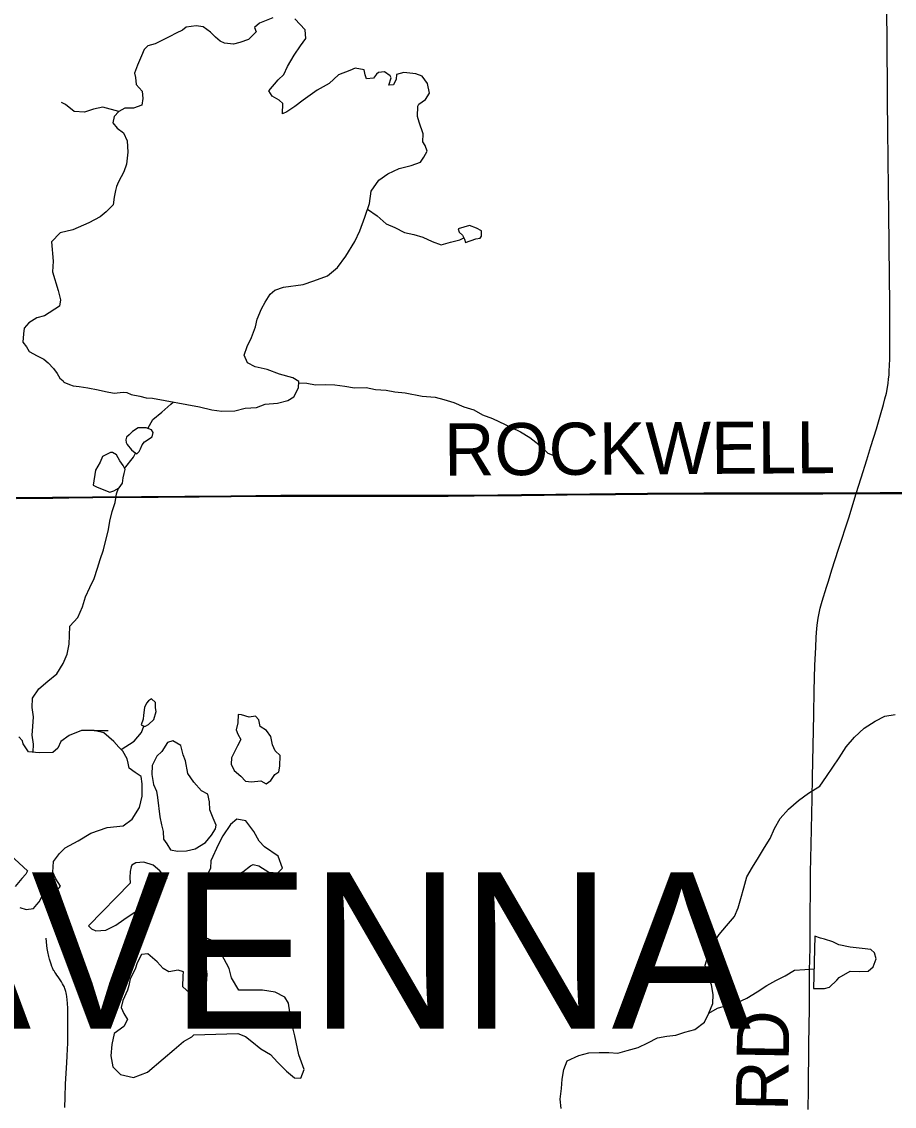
# Model space of a CAD drawing. Extents: x 0 to 34, y 0 to 22.
# Drawn here: x 24.299 to 25.25, y 14.945 to 16.128 of the extents above; entities that cross this region are included whole.
import ezdxf

# ---------------------------------------------------------------- set-up
doc = ezdxf.new("R2010")
doc.units = 0
for name, color, linetype in [('GM_X_Corporation', 7, 'Continuous'), ('GM_X_County_Road', 7, 'Continuous'), ('GM_X_County_Road_Text', 7, 'Continuous'), ('GM_X_Minor_Lake', 7, 'Continuous'), ('GM_X_Minor_River', 7, 'Continuous'), ('GM_X_Township_Road', 7, 'Continuous'), ('GM_X_Township_Text', 7, 'Continuous')]:
    doc.layers.add(name, color=color, linetype=linetype)

msp = doc.modelspace()

# ---------------------------------------------------------------- linework, layer by layer
at = {"layer": 'GM_X_Corporation'}
for points in [[(25.2604, 15.6138), (25.235, 15.6138), (25.2084, 15.6136), (25.172, 15.6134), (25.1329, 15.6134), (25.118, 15.6134), (25.0752, 15.6136), (25.0424, 15.6134), (24.9809, 15.6131), (24.9461, 15.6128), (24.9181, 15.6126), (24.8436, 15.6117), (24.792, 15.6111), (24.7634, 15.611), (24.7274, 15.6109), (24.7019, 15.6109), (24.6523, 15.6109), (24.6393, 15.6109), (24.6208, 15.611), (24.5813, 15.6109), (24.5268, 15.6104), (24.492, 15.61), (24.4765, 15.6099), (24.4473, 15.6097), (24.4292, 15.6096), (24.3758, 15.6093), (24.3497, 15.6089), (24.3323, 15.6087), (24.2926, 15.6084)], [(24.2926, 15.6084), (24.3323, 15.6087), (24.3497, 15.6089), (24.3758, 15.6093), (24.4292, 15.6096), (24.4473, 15.6097), (24.4765, 15.6099), (24.492, 15.61), (24.5268, 15.6104), (24.5813, 15.6109), (24.6208, 15.611), (24.6393, 15.6109), (24.6523, 15.6109), (24.7019, 15.6109), (24.7274, 15.6109), (24.7634, 15.611), (24.792, 15.6111), (24.8436, 15.6117), (24.9181, 15.6126), (24.9461, 15.6128), (24.9809, 15.6131), (25.0424, 15.6134), (25.0752, 15.6136), (25.118, 15.6134), (25.1329, 15.6134), (25.172, 15.6134), (25.2084, 15.6136), (25.235, 15.6138), (25.2604, 15.6138)]]:
    msp.add_lwpolyline(points, dxfattribs=at)
at = {"layer": 'GM_X_County_Road'}
for points in [[(25.2086, 15.6131), (25.2141, 15.6303), (25.2203, 15.6499), (25.2248, 15.6645), (25.2308, 15.6839), (25.2353, 15.6991), (25.2385, 15.7103), (25.2401, 15.7164), (25.2416, 15.7225), (25.2428, 15.7288), (25.2435, 15.7334), (25.2441, 15.738), (25.2446, 15.7426), (25.2448, 15.7465), (25.2453, 15.7598), (25.2454, 15.7669), (25.2454, 15.7757), (25.2454, 15.7911), (25.2453, 15.8193), (25.2445, 15.8826), (25.2444, 15.9209), (25.2441, 15.9449), (25.2436, 15.9788), (25.2433, 16.0086), (25.2431, 16.0193), (25.243, 16.0319), (25.2427, 16.0626), (25.2425, 16.0936), (25.242, 16.153)], [(25.2086, 15.6131), (25.2352, 15.6132), (25.2606, 15.6132), (25.2829, 15.6134), (25.309, 15.6134), (25.3301, 15.6135), (25.4755, 15.6146), (25.5271, 15.6148), (25.5526, 15.615), (25.7197, 15.6165), (25.7905, 15.6172), (25.849, 15.6177), (26.0069, 15.6183)], [(24.2928, 15.6079), (24.3325, 15.6082), (24.3499, 15.6084), (24.376, 15.6087), (24.4295, 15.6091), (24.4475, 15.6092), (24.4767, 15.6094), (24.4922, 15.6095), (24.527, 15.6098), (24.5815, 15.6103), (24.621, 15.6104), (24.6395, 15.6104), (24.6525, 15.6104), (24.7021, 15.6104), (24.7276, 15.6103), (24.7636, 15.6104), (24.7922, 15.6105), (24.8438, 15.6112), (24.9183, 15.612), (24.9463, 15.6122), (24.9811, 15.6125), (25.0426, 15.6128), (25.0754, 15.613), (25.1182, 15.6129), (25.1331, 15.6128), (25.1722, 15.6129), (25.2086, 15.6131)], [(25.1564, 14.9415), (25.1565, 14.9632), (25.1571, 15.0123), (25.1576, 15.0521), (25.1578, 15.0806), (25.1579, 15.0931), (25.1584, 15.1179), (25.1585, 15.134), (25.1585, 15.152), (25.1586, 15.1632), (25.1588, 15.1713), (25.159, 15.1998), (25.1596, 15.2303), (25.1606, 15.2806), (25.1609, 15.3038), (25.1625, 15.3723), (25.163, 15.3983), (25.1637, 15.4256), (25.1645, 15.4456), (25.165, 15.456), (25.1655, 15.4618), (25.1662, 15.4695), (25.1672, 15.4772), (25.1683, 15.4828), (25.1695, 15.488), (25.1717, 15.4957), (25.1763, 15.5112), (25.1783, 15.5177), (25.1822, 15.5301), (25.1895, 15.5525), (25.2006, 15.5868), (25.2086, 15.6131)]]:
    msp.add_lwpolyline(points, dxfattribs=at)
at = {"layer": 'GM_X_Minor_Lake'}
for p, q in [((24.7827, 15.887), (24.794, 15.8908)), ((24.4411, 15.7171), (24.4923, 15.7076)), ((24.4136, 15.6668), (24.4182, 15.6609)), ((24.381, 15.6203), (24.3946, 15.6147)), ((24.4324, 15.3799), (24.4313, 15.3715)), ((24.5338, 15.3382), (24.5275, 15.3249)), ((24.4468, 15.2818), (24.4493, 15.2606)), ((24.3458, 15.2268), (24.3601, 15.2345)), ((24.5131, 15.2307), (24.5049, 15.2125)), ((24.4375, 15.1638), (24.4573, 15.1939)), ((25.1637, 15.1303), (25.1623, 15.0734)), ((24.4863, 15.0227), (24.5344, 15.0242))]:
    msp.add_line(p, q, dxfattribs=at)
for points in [[(24.5149, 16.1064), (24.51, 16.1109), (24.5046, 16.1162), (24.4966, 16.1222), (24.4887, 16.1233), (24.4781, 16.1217), (24.474, 16.1186), (24.4672, 16.1151), (24.46, 16.1117), (24.4442, 16.1036), (24.4362, 16.1016), (24.4321, 16.0974), (24.4291, 16.0906), (24.4247, 16.0803), (24.4217, 16.0716), (24.4225, 16.067), (24.4233, 16.0594), (24.4298, 16.0519), (24.4306, 16.0439), (24.4296, 16.0367), (24.4205, 16.0336), (24.411, 16.0336), (24.4046, 16.0297), (24.3994, 16.0244), (24.3979, 16.0175), (24.4025, 16.0115), (24.4097, 16.0066), (24.4136, 15.9979), (24.4144, 15.9854), (24.413, 15.9725), (24.4101, 15.9641), (24.4041, 15.9531), (24.4019, 15.9481), (24.4008, 15.9436), (24.3993, 15.9364), (24.3982, 15.928), (24.3907, 15.9204), (24.3843, 15.915), (24.3719, 15.9085), (24.3545, 15.9008), (24.3406, 15.8976), (24.3312, 15.8877), (24.3329, 15.8665), (24.3322, 15.8551), (24.3384, 15.8346), (24.3408, 15.8244), (24.3397, 15.8176), (24.3235, 15.8068), (24.3152, 15.8049), (24.3065, 15.7995), (24.3013, 15.7934), (24.3006, 15.7873), (24.2999, 15.7782), (24.3037, 15.7733), (24.3068, 15.768), (24.3155, 15.7632), (24.3227, 15.7598), (24.3273, 15.7557), (24.3334, 15.7497), (24.3372, 15.744), (24.3403, 15.7391), (24.3437, 15.7361), (24.3445, 15.7346), (24.3506, 15.732), (24.3547, 15.7305), (24.3612, 15.7298), (24.3706, 15.7283), (24.382, 15.7261), (24.39, 15.7243), (24.3995, 15.7228), (24.4093, 15.7237), (24.4131, 15.7233), (24.418, 15.7211), (24.4275, 15.7193), (24.4343, 15.7174), (24.4411, 15.7171)], [(24.4923, 15.7076), (24.5059, 15.7043), (24.5169, 15.7029), (24.5309, 15.7034), (24.5423, 15.7061), (24.5548, 15.707), (24.5642, 15.7108), (24.5774, 15.7117), (24.5888, 15.7148), (24.5952, 15.7187), (24.6004, 15.7286), (24.6007, 15.7354), (24.5942, 15.7395), (24.5798, 15.7432), (24.5662, 15.7484), (24.5533, 15.7513), (24.5449, 15.7558), (24.5411, 15.7641), (24.5444, 15.7736), (24.5492, 15.7832), (24.5537, 15.7949), (24.5555, 15.8033), (24.56, 15.8147), (24.5641, 15.822), (24.5697, 15.8307), (24.5746, 15.8349), (24.584, 15.8384), (24.6056, 15.8412), (24.6173, 15.8451), (24.632, 15.8505), (24.6429, 15.8597), (24.6519, 15.8719), (24.662, 15.8879), (24.6672, 15.8997), (24.6727, 15.9146), (24.6779, 15.9294), (24.6797, 15.9431), (24.6879, 15.9549), (24.6977, 15.9618), (24.7102, 15.9676), (24.7234, 15.9711), (24.7336, 15.9746), (24.7373, 15.9799), (24.7407, 15.9864), (24.7387, 15.9928), (24.7361, 15.9966), (24.7364, 16.0053), (24.7321, 16.0182), (24.7302, 16.0242), (24.7305, 16.0356), (24.7316, 16.0379), (24.7391, 16.0429), (24.7432, 16.0497), (24.7412, 16.0603), (24.7355, 16.0683), (24.7283, 16.0709), (24.7154, 16.0723), (24.7075, 16.0703), (24.7068, 16.065), (24.7042, 16.0589), (24.6989, 16.0585), (24.7015, 16.0665), (24.7003, 16.0688), (24.6942, 16.0729), (24.6878, 16.0725), (24.6855, 16.0705), (24.6822, 16.0663), (24.6746, 16.0655), (24.673, 16.0697), (24.6722, 16.0754), (24.6624, 16.0772), (24.6564, 16.0745), (24.6439, 16.0698), (24.6338, 16.0603), (24.6209, 16.053), (24.6055, 16.0422), (24.5965, 16.0353), (24.5878, 16.0296), (24.5829, 16.0273), (24.5832, 16.0387), (24.5794, 16.042), (24.5718, 16.0465), (24.568, 16.0522), (24.5781, 16.0644), (24.5845, 16.0701), (24.5886, 16.0789), (24.5957, 16.0911), (24.6028, 16.1014), (24.6084, 16.1094), (24.6076, 16.1189), (24.5965, 16.1309)], [(24.5723, 16.1319), (24.5579, 16.1261), (24.5523, 16.1215), (24.5542, 16.1166), (24.546, 16.1085), (24.5365, 16.1051), (24.5297, 16.1031), (24.5199, 16.1045), (24.5149, 16.1064)], [(24.794, 15.8908), (24.7986, 15.8916), (24.8001, 15.8939), (24.8, 15.8996), (24.7947, 15.9026), (24.7871, 15.9056), (24.7746, 15.9017), (24.7758, 15.8983), (24.7792, 15.8949), (24.7815, 15.8907), (24.7827, 15.887)], [(24.4182, 15.6609), (24.4204, 15.6589), (24.4242, 15.6563), (24.4268, 15.659), (24.4283, 15.662), (24.4298, 15.6662), (24.4324, 15.6696), (24.4407, 15.675), (24.4418, 15.6796), (24.4403, 15.6826), (24.4342, 15.6848), (24.4255, 15.6847), (24.4195, 15.6809), (24.4157, 15.6771), (24.4127, 15.6748), (24.412, 15.6717), (24.4124, 15.6687), (24.4136, 15.6668)], [(24.3946, 15.6147), (24.3992, 15.6163), (24.4048, 15.6194), (24.4085, 15.6243), (24.4093, 15.6304), (24.4104, 15.6349), (24.4115, 15.6395), (24.4092, 15.6437), (24.4057, 15.6489), (24.4019, 15.6554), (24.3977, 15.658), (24.3954, 15.658), (24.3867, 15.6537), (24.3841, 15.6473), (24.3789, 15.6385), (24.3764, 15.6222), (24.381, 15.6203)], [(24.4313, 15.3715), (24.431, 15.367), (24.4288, 15.3609), (24.433, 15.359), (24.4367, 15.3613), (24.4427, 15.3667), (24.4453, 15.3754), (24.4445, 15.3796), (24.4445, 15.3853), (24.4403, 15.3891), (24.4369, 15.3871), (24.4347, 15.3845), (24.4324, 15.3799)], [(24.5275, 15.3249), (24.5271, 15.3181), (24.5302, 15.3112), (24.5375, 15.3049), (24.5428, 15.2996), (24.5492, 15.2989), (24.5595, 15.2997), (24.5652, 15.2967), (24.5704, 15.3002), (24.5745, 15.3067), (24.5791, 15.3097), (24.5801, 15.3158), (24.5804, 15.3276), (24.5751, 15.3324), (24.572, 15.3392), (24.5704, 15.3483), (24.5655, 15.3547), (24.5586, 15.3592), (24.557, 15.3664), (24.5536, 15.3702), (24.5468, 15.3694), (24.5381, 15.372), (24.5347, 15.3723), (24.5344, 15.3632), (24.5325, 15.3556), (24.5341, 15.3507), (24.5375, 15.3451), (24.5338, 15.3382)], [(24.3601, 15.2345), (24.3741, 15.2429), (24.3918, 15.2488), (24.4092, 15.2508), (24.419, 15.2581), (24.4272, 15.2706), (24.4298, 15.2832), (24.43, 15.2965), (24.4288, 15.3044), (24.4224, 15.3089), (24.4159, 15.3138), (24.4147, 15.3191), (24.4136, 15.324), (24.4089, 15.3323), (24.4044, 15.3365), (24.399, 15.3429), (24.388, 15.3523), (24.3777, 15.3548), (24.3637, 15.3547), (24.3505, 15.3493), (24.3411, 15.3428), (24.3378, 15.3356), (24.3325, 15.3306), (24.3177, 15.3305), (24.306, 15.3315), (24.3003, 15.3402), (24.2995, 15.3436), (24.2953, 15.3478)], [(24.4493, 15.2606), (24.4512, 15.2519), (24.4528, 15.2447), (24.4532, 15.2363), (24.4567, 15.2311), (24.4609, 15.2246), (24.4685, 15.2232), (24.4783, 15.2236), (24.4878, 15.2256), (24.4991, 15.2325), (24.5054, 15.2405), (24.5099, 15.2474), (24.5106, 15.2516), (24.5072, 15.2591), (24.5037, 15.2682), (24.5032, 15.2769), (24.5017, 15.2852), (24.4948, 15.289), (24.4864, 15.2984), (24.4799, 15.3078), (24.4772, 15.3215), (24.4748, 15.3283), (24.4721, 15.3385), (24.4634, 15.3434), (24.4577, 15.3418), (24.4513, 15.3319), (24.4461, 15.3269), (24.4409, 15.3166), (24.4406, 15.3068), (24.4422, 15.2958), (24.4456, 15.2886), (24.4468, 15.2818)], [(24.5049, 15.2125), (24.5046, 15.2045), (24.5012, 15.1976), (24.5062, 15.1916), (24.5172, 15.1917), (24.527, 15.1944), (24.5398, 15.2006), (24.5481, 15.2071), (24.5511, 15.2086), (24.5572, 15.2072), (24.5682, 15.2004), (24.578, 15.1994), (24.5829, 15.2047), (24.5783, 15.2176), (24.5634, 15.2277), (24.5577, 15.2341), (24.5516, 15.2447), (24.5431, 15.2564), (24.5333, 15.2582), (24.5261, 15.2521), (24.5179, 15.2399), (24.5131, 15.2307)], [(24.2964, 15.1616), (24.3036, 15.1594), (24.3115, 15.1606), (24.3149, 15.1651), (24.3175, 15.1678), (24.3216, 15.1754), (24.3204, 15.1811), (24.3208, 15.186), (24.3337, 15.1778), (24.3393, 15.1831), (24.3408, 15.185), (24.3359, 15.193), (24.3324, 15.2001), (24.3334, 15.2119), (24.3398, 15.2207), (24.3458, 15.2268)], [(24.2865, 15.2188), (24.3048, 15.2018), (24.3029, 15.198), (24.2988, 15.1934), (24.2916, 15.1847)], [(24.4573, 15.1939), (24.4535, 15.1965), (24.4493, 15.2018), (24.4421, 15.2078), (24.4319, 15.2111), (24.4232, 15.2103), (24.4186, 15.208), (24.4179, 15.2061), (24.4168, 15.2008), (24.4165, 15.1943), (24.4169, 15.1883), (24.3715, 15.1417), (24.3745, 15.1383), (24.3795, 15.1364), (24.3904, 15.1369), (24.4014, 15.1423), (24.41, 15.1488), (24.4213, 15.1561), (24.4292, 15.1599), (24.4375, 15.1638)], [(24.5344, 15.0242), (24.5427, 15.0209), (24.5496, 15.0156), (24.5595, 15.0077), (24.5698, 15.0014), (24.5774, 14.9931), (24.5873, 14.9833), (24.5961, 14.9758), (24.6029, 14.9755), (24.6066, 14.985), (24.6008, 15.0009), (24.5965, 15.0217), (24.5926, 15.0376), (24.5894, 15.0573), (24.5855, 15.0641), (24.5749, 15.0693), (24.5613, 15.0715), (24.551, 15.0714), (24.5355, 15.0716), (24.5275, 15.0849), (24.5247, 15.0951), (24.5163, 15.1109), (24.5109, 15.1192), (24.5052, 15.126), (24.4968, 15.1297), (24.492, 15.1244), (24.4951, 15.113), (24.499, 15.1006), (24.5006, 15.0888), (24.4999, 15.079), (24.4943, 15.0725), (24.4814, 15.0686), (24.4742, 15.0753), (24.4748, 15.0871), (24.4752, 15.0917), (24.4691, 15.0935), (24.4589, 15.0915), (24.4528, 15.0953), (24.4463, 15.1024), (24.436, 15.1111), (24.4292, 15.1103), (24.4244, 15.1015), (24.4222, 15.0943), (24.417, 15.084), (24.4155, 15.0768), (24.414, 15.0715), (24.4088, 15.0604), (24.407, 15.0525), (24.4101, 15.046), (24.4139, 15.0396), (24.4098, 15.032), (24.3993, 15.0243), (24.3967, 15.0122), (24.3957, 15), (24.398, 14.9879), (24.4064, 14.9797), (24.4205, 14.9763), (24.4359, 14.9822), (24.4528, 14.9967), (24.4649, 15.007), (24.475, 15.0154), (24.4841, 15.0208), (24.4863, 15.0227)], [(25.1623, 15.0734), (25.174, 15.0735), (25.1797, 15.075), (25.1875, 15.0823), (25.1902, 15.0854), (25.2022, 15.0923), (25.2124, 15.092), (25.2219, 15.0921), (25.2272, 15.097), (25.2305, 15.1058), (25.2286, 15.1122), (25.2247, 15.116), (25.2153, 15.117), (25.202, 15.1184), (25.1899, 15.121), (25.1831, 15.1244), (25.1743, 15.127), (25.1698, 15.1284), (25.1637, 15.1303)]]:
    msp.add_lwpolyline(points, dxfattribs=at)
at = {"layer": 'GM_X_Minor_River'}
for points in [[(24.4046, 16.0297), (24.3872, 16.0345), (24.377, 16.0325), (24.3672, 16.029), (24.3558, 16.0297), (24.3463, 16.0376), (24.3421, 16.0395)], [(24.6758, 15.9233), (24.6863, 15.9162), (24.6959, 15.9072), (24.7054, 15.9034), (24.716, 15.8978), (24.7262, 15.8956), (24.7361, 15.8927), (24.7464, 15.8882), (24.7562, 15.8845), (24.7661, 15.8872), (24.7763, 15.8899), (24.7809, 15.892)], [(24.6006, 15.7338), (24.6094, 15.7336), (24.6189, 15.7317), (24.6299, 15.7322), (24.6401, 15.7319), (24.6511, 15.7301), (24.6617, 15.7286), (24.6742, 15.7287), (24.6844, 15.7265), (24.6962, 15.7259), (24.7056, 15.724), (24.7166, 15.723), (24.7352, 15.7193), (24.7496, 15.7183), (24.7591, 15.7157), (24.7697, 15.7124), (24.7807, 15.7079), (24.7917, 15.7046), (24.8012, 15.699), (24.8122, 15.6949), (24.8327, 15.6852), (24.8426, 15.6803), (24.8529, 15.6744), (24.8624, 15.6668), (24.8723, 15.6571), (24.8788, 15.6548)], [(24.4363, 15.684), (24.4417, 15.694), (24.4515, 15.702), (24.4612, 15.7108), (24.4638, 15.7129)], [(24.4108, 15.6406), (24.4204, 15.6528), (24.4228, 15.6573)], [(24.311, 15.3311), (24.3116, 15.3399), (24.31, 15.3498), (24.3107, 15.3592), (24.3114, 15.3695), (24.3098, 15.3797), (24.3105, 15.39), (24.3172, 15.4003), (24.327, 15.4087), (24.3368, 15.4167), (24.3439, 15.4278), (24.3483, 15.438), (24.3505, 15.449), (24.3508, 15.4585), (24.3511, 15.4684), (24.3597, 15.4779), (24.3649, 15.4897), (24.3683, 15.5004), (24.3727, 15.5107), (24.3776, 15.5205), (24.3813, 15.5316), (24.3842, 15.5411), (24.3879, 15.5517), (24.3931, 15.5738), (24.3945, 15.5832), (24.3971, 15.5935), (24.4004, 15.6034), (24.4018, 15.6129), (24.4041, 15.619)], [(25.1459, 15.2784), (25.1568, 15.2865), (25.1692, 15.2941), (25.1763, 15.3044), (25.1831, 15.3147), (25.1902, 15.325), (25.1976, 15.3368), (25.207, 15.3475), (25.2172, 15.3574), (25.2292, 15.3651), (25.2398, 15.3705), (25.2511, 15.3721)], [(24.3777, 15.3548), (24.3929, 15.3549)], [(24.4072, 15.3339), (24.4213, 15.343), (24.4292, 15.3526), (24.4318, 15.3595)], [(24.887, 14.9424), (24.8858, 14.9526), (24.8872, 14.9644), (24.8879, 14.9746), (24.8897, 14.9849), (24.8934, 14.9944), (24.9062, 15.0002), (24.9172, 15.0033), (24.9282, 15.0037), (24.9388, 15.0034), (24.9486, 15.0028), (24.9588, 15.0059), (24.9709, 15.009), (24.9814, 15.014), (24.992, 15.0194), (25.0022, 15.0214), (25.012, 15.0226), (25.0218, 15.0257), (25.0328, 15.0288), (25.0433, 15.0368), (25.0478, 15.0464), (25.0523, 15.057), (25.0526, 15.0669), (25.051, 15.0775), (25.046, 15.0873), (25.044, 15.0987), (25.0477, 15.1108), (25.0521, 15.1211), (25.0592, 15.1321), (25.0671, 15.1417), (25.0761, 15.152), (25.0798, 15.1615), (25.0828, 15.1714), (25.0861, 15.1832), (25.0894, 15.1953), (25.0957, 15.2056), (25.1021, 15.2163), (25.1088, 15.2273), (25.1148, 15.2368), (25.1196, 15.2479), (25.1256, 15.2589), (25.135, 15.2688), (25.1459, 15.2784)], [(25.0478, 15.0464), (25.0576, 15.0521), (25.0674, 15.0548), (25.0784, 15.0576), (25.0893, 15.063), (25.1006, 15.0699), (25.1111, 15.0768), (25.1209, 15.0822), (25.1311, 15.0872), (25.1413, 15.0933), (25.1526, 15.0942), (25.1628, 15.0947)]]:
    msp.add_lwpolyline(points, dxfattribs=at)
at = {"layer": 'GM_X_Township_Road'}
msp.add_lwpolyline([(24.3455, 14.9437), (24.3459, 14.9548), (24.3464, 14.9694), (24.3478, 14.9923), (24.3482, 15.0001), (24.3485, 15.0071), (24.3488, 15.0138), (24.349, 15.0264), (24.349, 15.0394), (24.3489, 15.043), (24.3488, 15.0501), (24.3487, 15.0517), (24.3487, 15.0537), (24.3486, 15.0552), (24.3484, 15.0576), (24.3482, 15.0607), (24.3481, 15.0622), (24.3479, 15.0637), (24.3478, 15.0647), (24.3475, 15.0668), (24.3471, 15.0687), (24.3468, 15.0702), (24.3464, 15.0713), (24.3461, 15.0724), (24.3457, 15.0734), (24.3451, 15.0749), (24.3442, 15.0765), (24.3431, 15.0785), (24.3419, 15.0805), (24.3396, 15.0838), (24.3382, 15.086), (24.3369, 15.0879), (24.3357, 15.0896), (24.3347, 15.0911), (24.3338, 15.0926), (24.3334, 15.0931), (24.333, 15.0941), (24.3325, 15.095), (24.3321, 15.0959), (24.3315, 15.0974), (24.3307, 15.0998), (24.3289, 15.1052), (24.3281, 15.1083), (24.3271, 15.1132), (24.3265, 15.117), (24.326, 15.1204), (24.3251, 15.1283)], dxfattribs=at)

# ---------------------------------------------------------------- texts
at = {"layer": 'GM_X_County_Road_Text'}
for s, rotation, p in [('ROCKWELL', 0.3709, (24.7594, 15.6327)), ('RD', 89.0138, (25.1341, 14.9393))]:
    msp.add_text(s, height=0.05682, rotation=rotation, dxfattribs=at).set_placement(p)
at = {"layer": 'GM_X_Township_Text'}
msp.add_text('RAVENNA', height=0.17045, rotation=0, dxfattribs=at).set_placement((23.9921, 15.0296))

doc.saveas('drawing.dxf')
